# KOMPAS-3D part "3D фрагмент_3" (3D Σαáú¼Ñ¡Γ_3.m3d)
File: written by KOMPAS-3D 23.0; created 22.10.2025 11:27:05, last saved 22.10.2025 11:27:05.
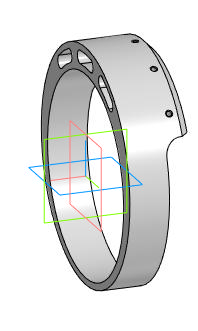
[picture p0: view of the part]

Document properties: Автор: ARM_513_VVK; Полное имя файла: F:\Демо\Демо вариант авиация\3D фрагмент_3.m3d

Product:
- Part/product: 3D фрагмент_3

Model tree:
1. Операция без истории:1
